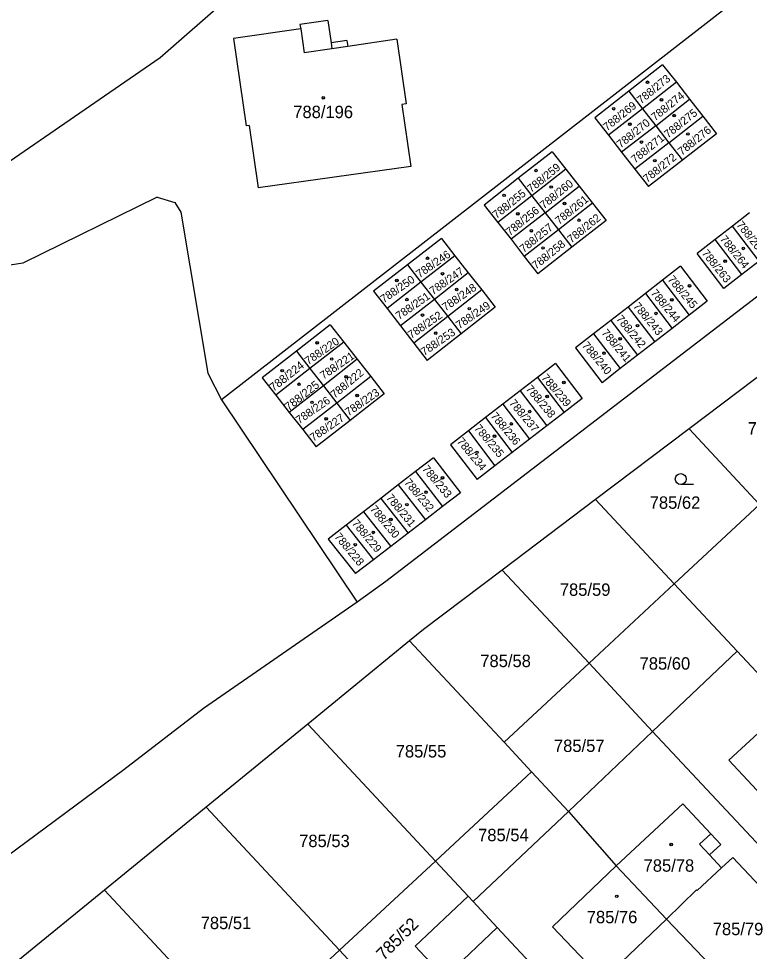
# Model space of a CAD drawing. Extents: x -593183 to -588034, y -1130415 to -1124994.
# Drawn here: x -591754 to -591653.6, y -1128558.2 to -1128430.1 of the extents above; entities that cross this region are included whole.
import ezdxf

# ---------------------------------------------------------------- set-up
doc = ezdxf.new("R2010")
doc.units = 0
for name, color, linetype in [('Vrstva 1', 7, 'Continuous'), ('Vrstva 18', 7, 'Continuous'), ('Vrstva 19', 7, 'Continuous'), ('Vrstva 25', 7, 'Continuous'), ('Vrstva 4', 7, 'Continuous')]:
    doc.layers.add(name, color=color, linetype=linetype)

msp = doc.modelspace()

# ---------------------------------------------------------------- linework, layer by layer
at = {"layer": 'Vrstva 1'}
for p, q in [((-591718.9, -1128421.81), (-591734.52, -1128435.48)), ((-591655.62, -1128427.75), (-591726.1, -1128482.46)), ((-591711.49, -1128430.35), (-591715.32, -1128430.91)), ((-591715.32, -1128430.91), (-591715.21, -1128431.51)), ((-591711.49, -1128430.35), (-591711.05, -1128433.44)), ((-591715.21, -1128431.51), (-591724.44, -1128432.82)), ((-591724.44, -1128432.82), (-591722.7, -1128444.85)), ((-591708.86, -1128433.12), (-591711.05, -1128433.44)), ((-591708.86, -1128433.12), (-591708.75, -1128433.92)), ((-591702, -1128432.94), (-591708.75, -1128433.92)), ((-591702, -1128432.94), (-591700.72, -1128441.79)), ((-591734.52, -1128435.48), (-591756.65, -1128450.69)), ((-591665.48, -1128436.43), (-591670.14, -1128440.08)), ((-591665.48, -1128436.43), (-591663.6, -1128438.84)), ((-591663.6, -1128438.84), (-591668.27, -1128442.48)), ((-591663.6, -1128438.84), (-591661.78, -1128441.18)), ((-591670.14, -1128440.08), (-591674.81, -1128443.72)), ((-591670.14, -1128440.08), (-591668.27, -1128442.48)), ((-591666.44, -1128444.82), (-591661.78, -1128441.18)), ((-591661.78, -1128441.18), (-591659.95, -1128443.52)), ((-591700.72, -1128441.79), (-591701.31, -1128441.88)), ((-591701.31, -1128441.88), (-591700.09, -1128450.42)), ((-591668.27, -1128442.48), (-591672.94, -1128446.12)), ((-591668.27, -1128442.48), (-591666.44, -1128444.82)), ((-591674.81, -1128443.72), (-591672.94, -1128446.12)), ((-591664.61, -1128447.16), (-591659.95, -1128443.52)), ((-591659.95, -1128443.52), (-591658.07, -1128445.93)), ((-591722.3, -1128444.79), (-591722.7, -1128444.85)), ((-591722.3, -1128444.79), (-591721.07, -1128453.34)), ((-591666.44, -1128444.82), (-591671.12, -1128448.45)), ((-591666.44, -1128444.82), (-591664.61, -1128447.16)), ((-591672.94, -1128446.12), (-591671.12, -1128448.45)), ((-591658.07, -1128445.93), (-591662.74, -1128449.56)), ((-591664.61, -1128447.16), (-591669.29, -1128450.78)), ((-591664.61, -1128447.16), (-591662.74, -1128449.56)), ((-591680.67, -1128448.38), (-591685.33, -1128452.04)), ((-591680.67, -1128448.38), (-591678.8, -1128450.77)), ((-591671.12, -1128448.45), (-591669.29, -1128450.78)), ((-591700.09, -1128450.42), (-591721.07, -1128453.34)), ((-591662.74, -1128449.56), (-591667.42, -1128453.18)), ((-591678.8, -1128450.77), (-591683.46, -1128454.43)), ((-591678.8, -1128450.77), (-591676.96, -1128453.12)), ((-591669.29, -1128450.78), (-591667.42, -1128453.18)), ((-591685.33, -1128452.04), (-591689.99, -1128455.71)), ((-591685.33, -1128452.04), (-591683.46, -1128454.43)), ((-591681.64, -1128456.77), (-591676.96, -1128453.12)), ((-591676.96, -1128453.12), (-591675.12, -1128455.46)), ((-591683.46, -1128454.43), (-591688.13, -1128458.09)), ((-591683.46, -1128454.43), (-591681.64, -1128456.77)), ((-591734.93, -1128454.61), (-591753.4, -1128463.71)), ((-591734.93, -1128454.61), (-591732.53, -1128455.37)), ((-591732.53, -1128455.37), (-591731.69, -1128456.67)), ((-591689.99, -1128455.71), (-591688.13, -1128458.09)), ((-591675.12, -1128455.46), (-591679.81, -1128459.11)), ((-591675.12, -1128455.46), (-591673.25, -1128457.85)), ((-591731.69, -1128456.67), (-591727.99, -1128478.8)), ((-591681.64, -1128456.77), (-591686.31, -1128460.42)), ((-591681.64, -1128456.77), (-591679.81, -1128459.11)), ((-591653.53, -1128456.78), (-591655.89, -1128458.62)), ((-591688.13, -1128458.09), (-591686.31, -1128460.42)), ((-591673.25, -1128457.85), (-591677.94, -1128461.5)), ((-591679.81, -1128459.11), (-591684.49, -1128462.76)), ((-591679.81, -1128459.11), (-591677.94, -1128461.5)), ((-591655.89, -1128458.62), (-591658.25, -1128460.46)), ((-591652.22, -1128463.4), (-591655.89, -1128458.62)), ((-591695.89, -1128460.29), (-591700.54, -1128463.92)), ((-591695.89, -1128460.29), (-591694.03, -1128462.67)), ((-591686.31, -1128460.42), (-591684.49, -1128462.76)), ((-591658.25, -1128460.46), (-591660.73, -1128462.39)), ((-591654.59, -1128465.24), (-591658.25, -1128460.46)), ((-591677.94, -1128461.5), (-591682.63, -1128465.14)), ((-591694.03, -1128462.67), (-591698.69, -1128466.3)), ((-591694.03, -1128462.67), (-591692.19, -1128465.03)), ((-591684.49, -1128462.76), (-591682.63, -1128465.14)), ((-591657.08, -1128467.18), (-591660.73, -1128462.39)), ((-591652.22, -1128463.4), (-591654.59, -1128465.24)), ((-591753.4, -1128463.71), (-591768.38, -1128465.92)), ((-591700.54, -1128463.92), (-591705.2, -1128467.55)), ((-591646.77, -1128463.88), (-591703.54, -1128507.42)), ((-591700.54, -1128463.92), (-591698.69, -1128466.3)), ((-591663.01, -1128464.12), (-591665.48, -1128466.04)), ((-591663.01, -1128464.12), (-591659.35, -1128468.91)), ((-591692.19, -1128465.03), (-591696.85, -1128468.67)), ((-591692.19, -1128465.03), (-591690.35, -1128467.38)), ((-591654.59, -1128465.24), (-591657.08, -1128467.18)), ((-591698.69, -1128466.3), (-591703.35, -1128469.94)), ((-591698.69, -1128466.3), (-591696.85, -1128468.67)), ((-591665.48, -1128466.04), (-591667.85, -1128467.88)), ((-591665.48, -1128466.04), (-591661.82, -1128470.82)), ((-591705.2, -1128467.55), (-591703.35, -1128469.94)), ((-591690.35, -1128467.38), (-591695.02, -1128471.03)), ((-591690.35, -1128467.38), (-591688.5, -1128469.75)), ((-591667.85, -1128467.88), (-591670.22, -1128469.72)), ((-591667.85, -1128467.88), (-591664.19, -1128472.67)), ((-591696.85, -1128468.67), (-591701.52, -1128472.31)), ((-591696.85, -1128468.67), (-591695.02, -1128471.03)), ((-591688.5, -1128469.75), (-591693.17, -1128473.41)), ((-591670.22, -1128469.72), (-591672.59, -1128471.57)), ((-591670.22, -1128469.72), (-591666.56, -1128474.51)), ((-591659.35, -1128468.91), (-591661.82, -1128470.82)), ((-591703.35, -1128469.94), (-591701.52, -1128472.31)), ((-591695.02, -1128471.03), (-591699.69, -1128474.68)), ((-591695.02, -1128471.03), (-591693.17, -1128473.41)), ((-591661.82, -1128470.82), (-591664.19, -1128472.67)), ((-591711.16, -1128472.15), (-591715.8, -1128475.78)), ((-591711.16, -1128472.15), (-591709.3, -1128474.53)), ((-591701.52, -1128472.31), (-591699.69, -1128474.68)), ((-591672.59, -1128471.57), (-591674.97, -1128473.41)), ((-591672.59, -1128471.57), (-591668.93, -1128476.35)), ((-591693.17, -1128473.41), (-591697.84, -1128477.07)), ((-591674.97, -1128473.41), (-591677.45, -1128475.34)), ((-591674.97, -1128473.41), (-591671.3, -1128478.19)), ((-591664.19, -1128472.67), (-591666.56, -1128474.51)), ((-591709.3, -1128474.53), (-591713.95, -1128478.16)), ((-591709.3, -1128474.53), (-591707.44, -1128476.9)), ((-591699.69, -1128474.68), (-591697.84, -1128477.07)), ((-591666.56, -1128474.51), (-591668.93, -1128476.35)), ((-591715.8, -1128475.78), (-591720.49, -1128479.45)), ((-591715.8, -1128475.78), (-591713.95, -1128478.16)), ((-591677.45, -1128475.34), (-591673.78, -1128480.12)), ((-591707.44, -1128476.9), (-591712.1, -1128480.54)), ((-591707.44, -1128476.9), (-591705.59, -1128479.28)), ((-591680.19, -1128477.49), (-591682.68, -1128479.42)), ((-591680.19, -1128477.49), (-591676.52, -1128482.29)), ((-591668.93, -1128476.35), (-591671.3, -1128478.19)), ((-591649.07, -1128476.82), (-591661.85, -1128486.47)), ((-591713.95, -1128478.16), (-591718.64, -1128481.82)), ((-591713.95, -1128478.16), (-591712.1, -1128480.54)), ((-591671.3, -1128478.19), (-591673.78, -1128480.12)), ((-591727.99, -1128478.8), (-591726.1, -1128482.46)), ((-591720.49, -1128479.45), (-591718.64, -1128481.82)), ((-591705.59, -1128479.28), (-591710.25, -1128482.92)), ((-591705.59, -1128479.28), (-591703.73, -1128481.66)), ((-591682.68, -1128479.42), (-591685.06, -1128481.25)), ((-591682.68, -1128479.42), (-591679.01, -1128484.21)), ((-591712.1, -1128480.54), (-591716.78, -1128484.2)), ((-591712.1, -1128480.54), (-591710.25, -1128482.92)), ((-591685.06, -1128481.25), (-591687.44, -1128483.08)), ((-591685.06, -1128481.25), (-591681.39, -1128486.04)), ((-591726.1, -1128482.46), (-591707.48, -1128510.26)), ((-591718.64, -1128481.82), (-591716.78, -1128484.2)), ((-591703.73, -1128481.66), (-591708.4, -1128485.3)), ((-591676.52, -1128482.29), (-591679.01, -1128484.21)), ((-591710.25, -1128482.92), (-591714.92, -1128486.57)), ((-591710.25, -1128482.92), (-591708.4, -1128485.3)), ((-591687.44, -1128483.08), (-591689.81, -1128484.91)), ((-591687.44, -1128483.08), (-591683.76, -1128487.86)), ((-591716.78, -1128484.2), (-591714.92, -1128486.57)), ((-591689.81, -1128484.91), (-591692.18, -1128486.75)), ((-591689.81, -1128484.91), (-591686.14, -1128489.69)), ((-591679.01, -1128484.21), (-591681.39, -1128486.04)), ((-591708.4, -1128485.3), (-591713.07, -1128488.94)), ((-591681.39, -1128486.04), (-591683.76, -1128487.86)), ((-591661.85, -1128486.47), (-591674.71, -1128496.18)), ((-591661.85, -1128486.47), (-591652.18, -1128496.84)), ((-591714.92, -1128486.57), (-591713.07, -1128488.94)), ((-591692.18, -1128486.75), (-591694.64, -1128488.64)), ((-591692.18, -1128486.75), (-591688.52, -1128491.52)), ((-591694.64, -1128488.64), (-591690.97, -1128493.41)), ((-591683.76, -1128487.86), (-591686.14, -1128489.69)), ((-591686.14, -1128489.69), (-591688.52, -1128491.52)), ((-591696.95, -1128490.42), (-591699.42, -1128492.33)), ((-591696.95, -1128490.42), (-591693.24, -1128495.23)), ((-591688.52, -1128491.52), (-591690.97, -1128493.41)), ((-591699.42, -1128492.33), (-591701.81, -1128494.17)), ((-591699.42, -1128492.33), (-591695.71, -1128497.13)), ((-591701.81, -1128494.17), (-591704.19, -1128496.01)), ((-591701.81, -1128494.17), (-591698.09, -1128498.96)), ((-591693.24, -1128495.23), (-591695.71, -1128497.13)), ((-591704.19, -1128496.01), (-591706.57, -1128497.85)), ((-591704.19, -1128496.01), (-591700.47, -1128500.78)), ((-591674.71, -1128496.18), (-591687.54, -1128505.86)), ((-591674.71, -1128496.18), (-591663.9, -1128507.76)), ((-591706.57, -1128497.85), (-591708.95, -1128499.69)), ((-591706.57, -1128497.85), (-591702.85, -1128502.61)), ((-591695.71, -1128497.13), (-591698.09, -1128498.96)), ((-591652.18, -1128496.84), (-591663.9, -1128507.76)), ((-591698.09, -1128498.96), (-591700.47, -1128500.78)), ((-591708.95, -1128499.69), (-591711.43, -1128501.61)), ((-591708.95, -1128499.69), (-591705.23, -1128504.44)), ((-591711.43, -1128501.61), (-591707.71, -1128506.34)), ((-591700.47, -1128500.78), (-591702.85, -1128502.61)), ((-591702.85, -1128502.61), (-591705.23, -1128504.44)), ((-591705.23, -1128504.44), (-591707.71, -1128506.34)), ((-591687.54, -1128505.86), (-591698.36, -1128514.03)), ((-591687.54, -1128505.86), (-591675.6, -1128518.65)), ((-591703.54, -1128507.42), (-591707.48, -1128510.26)), ((-591663.9, -1128507.76), (-591675.6, -1128518.65)), ((-591663.9, -1128507.76), (-591655.26, -1128517.01)), ((-591707.48, -1128510.26), (-591728.56, -1128524.87)), ((-591698.36, -1128514.03), (-591700.26, -1128515.58)), ((-591700.26, -1128515.58), (-591714.25, -1128527.01)), ((-591700.26, -1128515.58), (-591687.28, -1128529.51)), ((-591655.26, -1128517.01), (-591666.86, -1128528.02)), ((-591655.26, -1128517.01), (-591648.29, -1128524.48)), ((-591675.6, -1128518.65), (-591687.28, -1128529.51)), ((-591675.6, -1128518.65), (-591666.86, -1128528.02)), ((-591728.56, -1128524.87), (-591739.53, -1128533.3)), ((-591714.25, -1128527.01), (-591728.21, -1128538.42)), ((-591714.25, -1128527.01), (-591696.68, -1128545.85)), ((-591666.86, -1128528.02), (-591678.41, -1128539.03)), ((-591666.86, -1128528.02), (-591641.62, -1128555.07)), ((-591687.28, -1128529.51), (-591683.51, -1128533.56)), ((-591739.53, -1128533.3), (-591766.52, -1128553.31)), ((-591683.51, -1128533.56), (-591696.68, -1128545.85)), ((-591683.51, -1128533.56), (-591678.41, -1128539.03)), ((-591728.21, -1128538.42), (-591742.17, -1128549.82)), ((-591728.21, -1128538.42), (-591709.88, -1128558.08)), ((-591678.41, -1128539.03), (-591691.52, -1128551.39)), ((-591678.41, -1128539.03), (-591671.85, -1128546.49)), ((-591655.86, -1128545.33), (-591657.39, -1128546.76)), ((-591655.86, -1128545.33), (-591644.37, -1128557.61)), ((-591696.68, -1128545.85), (-591709.88, -1128558.08)), ((-591696.68, -1128545.85), (-591692.2, -1128550.66)), ((-591671.85, -1128546.49), (-591664.94, -1128553.81)), ((-591657.39, -1128546.76), (-591660.74, -1128549.88)), ((-591742.17, -1128549.82), (-591753.86, -1128559.37)), ((-591742.17, -1128549.82), (-591729.12, -1128563.82)), ((-591660.81, -1128549.81), (-591664.94, -1128553.81)), ((-591660.81, -1128549.81), (-591660.74, -1128549.88)), ((-591692.2, -1128550.66), (-591699.48, -1128557.52)), ((-591692.2, -1128550.66), (-591691.52, -1128551.39)), ((-591691.52, -1128551.39), (-591688.2, -1128554.95)), ((-591664.94, -1128553.81), (-591672.15, -1128560.71)), ((-591664.94, -1128553.81), (-591653.34, -1128565.95)), ((-591688.2, -1128554.95), (-591666.52, -1128578.2)), ((-591709.88, -1128558.08), (-591723.08, -1128570.3)), ((-591709.88, -1128558.08), (-591703.25, -1128565.19)), ((-591699.48, -1128557.52), (-591697.44, -1128559.71))]:
    msp.add_line(p, q, dxfattribs=at)
at = {"layer": 'Vrstva 25'}
msp.add_line((-591661.25, -1128494.11), (-591663, -1128494.11), dxfattribs=at)
for centre, radius in [((-591667.57, -1128438.84), 0.175), ((-591667.57, -1128438.84), 0.15), ((-591712.11, -1128440.99), 0.175), ((-591712.11, -1128440.99), 0.15), ((-591665.65, -1128441.25), 0.175), ((-591665.65, -1128441.25), 0.15), ((-591672.21, -1128442.48), 0.175), ((-591672.21, -1128442.48), 0.15), ((-591663.9, -1128443.42), 0.175), ((-591663.9, -1128443.42), 0.15), ((-591669.99, -1128444.61), 0.175), ((-591669.99, -1128444.61), 0.15), ((-591662.01, -1128445.95), 0.175), ((-591662.01, -1128445.95), 0.15), ((-591668.4, -1128447.06), 0.175), ((-591668.4, -1128447.06), 0.15), ((-591666.56, -1128449.62), 0.175), ((-591666.56, -1128449.62), 0.15), ((-591682.88, -1128450.98), 0.175), ((-591682.88, -1128450.98), 0.15), ((-591680.81, -1128453.24), 0.175), ((-591680.81, -1128453.24), 0.15), ((-591687.27, -1128454.37), 0.175), ((-591687.27, -1128454.37), 0.15), ((-591678.96, -1128455.5), 0.175), ((-591678.96, -1128455.5), 0.15), ((-591685.39, -1128456.92), 0.175), ((-591685.39, -1128456.92), 0.15), ((-591676.98, -1128457.8), 0.175), ((-591676.98, -1128457.8), 0.15), ((-591683.52, -1128459.25), 0.175), ((-591683.52, -1128459.25), 0.15), ((-591681.92, -1128461.61), 0.175), ((-591681.92, -1128461.61), 0.15), ((-591654.4, -1128461.67), 0.175), ((-591654.4, -1128461.67), 0.15), ((-591697.78, -1128463.02), 0.175), ((-591697.78, -1128463.02), 0.15), ((-591656.89, -1128463.43), 0.175), ((-591656.89, -1128463.43), 0.15), ((-591702, -1128466.08), 0.175), ((-591702, -1128466.08), 0.15), ((-591695.74, -1128465.15), 0.175), ((-591695.74, -1128465.15), 0.15), ((-591693.78, -1128467.32), 0.175), ((-591693.78, -1128467.32), 0.15), ((-591661.78, -1128466.82), 0.175), ((-591661.78, -1128466.82), 0.15), ((-591700.62, -1128468.7), 0.175), ((-591700.62, -1128468.7), 0.15), ((-591692.05, -1128469.94), 0.175), ((-591692.05, -1128469.94), 0.15), ((-591664.22, -1128468.73), 0.175), ((-591664.22, -1128468.73), 0.15), ((-591698.49, -1128470.83), 0.175), ((-591698.49, -1128470.83), 0.15), ((-591666.4, -1128470.6), 0.175), ((-591666.4, -1128470.6), 0.15), ((-591668.93, -1128472.28), 0.175), ((-591668.93, -1128472.28), 0.15), ((-591696.67, -1128473.32), 0.175), ((-591696.67, -1128473.32), 0.15), ((-591712.96, -1128474.65), 0.175), ((-591712.96, -1128474.65), 0.15), ((-591671.32, -1128474.1), 0.175), ((-591671.32, -1128474.1), 0.15), ((-591673.54, -1128476.06), 0.175), ((-591673.54, -1128476.06), 0.15), ((-591710.96, -1128476.87), 0.175), ((-591710.96, -1128476.87), 0.15), ((-591717.76, -1128478.46), 0.175), ((-591717.76, -1128478.46), 0.15), ((-591708.97, -1128479.31), 0.175), ((-591708.97, -1128479.31), 0.15), ((-591679.05, -1128480.1), 0.175), ((-591679.05, -1128480.1), 0.15), ((-591715.45, -1128480.33), 0.175), ((-591715.45, -1128480.33), 0.15), ((-591707.46, -1128481.88), 0.175), ((-591707.46, -1128481.88), 0.15), ((-591681.36, -1128482.01), 0.175), ((-591681.36, -1128482.01), 0.15), ((-591713.67, -1128482.81), 0.175), ((-591713.67, -1128482.81), 0.15), ((-591711.72, -1128485.08), 0.175), ((-591711.72, -1128485.08), 0.15), ((-591683.75, -1128484.09), 0.175), ((-591683.75, -1128484.09), 0.15), ((-591686.28, -1128485.78), 0.175), ((-591686.28, -1128485.78), 0.15), ((-591688.59, -1128487.47), 0.175), ((-591688.59, -1128487.47), 0.15), ((-591690.99, -1128489.69), 0.175), ((-591690.99, -1128489.69), 0.15), ((-591663, -1128493.36), 0.75), ((-591695.74, -1128493.19), 0.175), ((-591695.74, -1128493.19), 0.15), ((-591698, -1128495.15), 0.175), ((-591698, -1128495.15), 0.15), ((-591700.62, -1128496.88), 0.175), ((-591700.62, -1128496.88), 0.15), ((-591702.84, -1128498.92), 0.175), ((-591702.84, -1128498.92), 0.15), ((-591705.24, -1128500.69), 0.175), ((-591705.24, -1128500.69), 0.15), ((-591707.72, -1128502.38), 0.175), ((-591707.72, -1128502.38), 0.15), ((-591664.3, -1128543.56), 0.175), ((-591664.3, -1128543.56), 0.15), ((-591671.79, -1128550.69), 0.175), ((-591671.79, -1128550.69), 0.15)]:
    msp.add_circle(centre, radius, dxfattribs=at)
at = {"layer": 'Vrstva 4'}
for p, q in [((-591715.21, -1128431.51), (-591714.74, -1128434.78)), ((-591711.05, -1128433.44), (-591710.94, -1128434.23)), ((-591708.75, -1128433.92), (-591710.94, -1128434.23)), ((-591710.94, -1128434.23), (-591714.74, -1128434.78)), ((-591648.29, -1128524.48), (-591656.39, -1128531.96)), ((-591656.39, -1128531.96), (-591649.41, -1128539.46)), ((-591662.73, -1128537.96), (-591671.85, -1128546.49)), ((-591662.73, -1128537.96), (-591658.87, -1128542.1)), ((-591658.87, -1128542.1), (-591660.4, -1128543.53)), ((-591658.87, -1128542.1), (-591657.51, -1128543.56)), ((-591660.4, -1128543.53), (-591659.04, -1128544.99)), ((-591657.51, -1128543.56), (-591659.04, -1128544.99)), ((-591659.04, -1128544.99), (-591657.39, -1128546.76)), ((-591671.85, -1128546.49), (-591680.62, -1128554.89)), ((-591688.2, -1128554.95), (-591695.46, -1128561.82)), ((-591680.62, -1128554.89), (-591675.08, -1128560.67))]:
    msp.add_line(p, q, dxfattribs=at)

# ---------------------------------------------------------------- texts
at = {"layer": 'Vrstva 18'}
for s, p in [('785/63', (-591653.8, -1128487.24)), ('785/62', (-591667.26, -1128497.44)), ('785/59', (-591679.61, -1128509.4)), ('785/58', (-591690.54, -1128519.19)), ('785/60', (-591668.65, -1128519.54)), ('785/55', (-591702.16, -1128531.61)), ('785/57', (-591680.42, -1128530.85)), ('785/54', (-591690.84, -1128543.11)), ('785/53', (-591715.43, -1128543.92)), ('785/51', (-591728.96, -1128555.19)), ('785/79', (-591658.6, -1128556.02))]:
    msp.add_text(s, height=1.7, dxfattribs=at).set_placement(p)
msp.add_text('785/52', height=1.7, rotation=45.0357, dxfattribs=at).set_placement((-591703.81, -1128559.57))
at = {"layer": 'Vrstva 19'}
for s, height, rotation, p in [('788/273', 1.1, 38.8603, (-591668.45, -1128441.88)), ('788/274', 1.1, 38.8603, (-591666.52, -1128444.22)), ('788/269', 1.1, 38.8603, (-591673.12, -1128445.59)), ('788/275', 1.1, 38.8603, (-591664.74, -1128446.58)), ('788/270', 1.1, 38.8603, (-591671.25, -1128447.96)), ('788/276', 1.1, 38.8603, (-591662.84, -1128448.95)), ('788/271', 1.1, 38.8603, (-591669.27, -1128450.04)), ('788/272', 1.1, 38.8603, (-591667.61, -1128452.69)), ('788/259', 1.1, 38.8603, (-591683.55, -1128454.06)), ('788/260', 1.1, 38.8603, (-591681.8, -1128456.31)), ('788/255', 1.1, 38.8603, (-591688.31, -1128457.65)), ('788/261', 1.1, 38.8603, (-591679.71, -1128458.46)), ('788/256', 1.1, 38.8603, (-591686.48, -1128459.99)), ('788/262', 1.1, 38.8603, (-591678.03, -1128461.01)), ('788/257', 1.1, 38.8603, (-591684.58, -1128462.32)), ('788/265', 1.1, 308.7843, (-591655.41, -1128458.46)), ('788/258', 1.1, 38.8603, (-591682.89, -1128464.6)), ('788/264', 1.1, 308.7843, (-591657.68, -1128460.41)), ('788/246', 1.1, 34.6242, (-591698.89, -1128465.78)), ('788/263', 1.1, 308.7843, (-591660.18, -1128462.36)), ('788/247', 1.1, 34.6242, (-591697.05, -1128468.1)), ('788/250', 1.1, 34.6242, (-591703.8, -1128469.22)), ('788/245', 1.1, 309.9079, (-591664.86, -1128465.96)), ('788/248', 1.1, 34.6242, (-591695.32, -1128470.33)), ('788/244', 1.1, 309.9079, (-591667.2, -1128467.85)), ('788/251', 1.1, 34.6242, (-591701.7, -1128471.52)), ('788/249', 1.1, 34.6242, (-591693.42, -1128472.79)), ('788/243', 1.1, 309.9079, (-591669.59, -1128469.65)), ('788/252', 1.1, 34.6242, (-591700.02, -1128474.13)), ('788/242', 1.1, 309.9079, (-591671.95, -1128471.4)), ('788/253', 1.1, 34.6242, (-591698.24, -1128476.47)), ('788/241', 1.1, 309.9079, (-591673.96, -1128473.32)), ('788/220', 1.1, 34.6242, (-591714.18, -1128477.72)), ('788/240', 1.1, 309.9079, (-591676.63, -1128475.04)), ('788/221', 1.1, 34.6242, (-591712.09, -1128479.72)), ('788/224', 1.14, 38.4859, (-591718.94, -1128481.38)), ('788/222', 1.1, 39.9018, (-591710.54, -1128482.34)), ('788/225', 1.14, 38.3475, (-591716.86, -1128484.05)), ('788/239', 1.1, 309.9079, (-591682.21, -1128479.48)), ('788/223', 1.1, 34.6242, (-591708.65, -1128484.75)), ('788/238', 1.1, 309.9079, (-591684.36, -1128481)), ('788/226', 1.1, 34.6242, (-591715.42, -1128485.84)), ('788/237', 1.1, 309.9079, (-591686.65, -1128482.96)), ('788/227', 1.1, 34.6242, (-591713.48, -1128488.24)), ('788/236', 1.1, 309.9079, (-591689.19, -1128484.74)), ('788/235', 1.1, 309.9079, (-591691.43, -1128486.42)), ('788/234', 1.1, 309.9079, (-591693.83, -1128488.23)), ('788/233', 1.1, 309.9079, (-591698.6, -1128492)), ('788/232', 1.1, 309.9079, (-591701.06, -1128493.87)), ('788/231', 1.1, 309.9079, (-591703.55, -1128495.97)), ('788/230', 1.1, 309.9079, (-591705.77, -1128497.52)), ('788/229', 1.1, 309.9079, (-591708.26, -1128499.48)), ('788/228', 1.1, 309.9079, (-591710.66, -1128501.32))]:
    msp.add_text(s, height=height, rotation=rotation, dxfattribs=at).set_placement(p)
for s, p in [('788/196', (-591716.24, -1128443.77)), ('785/78', (-591668.1, -1128547.3)), ('785/76', (-591675.91, -1128554.38))]:
    msp.add_text(s, height=1.7, dxfattribs=at).set_placement(p)

doc.saveas('drawing.dxf')
